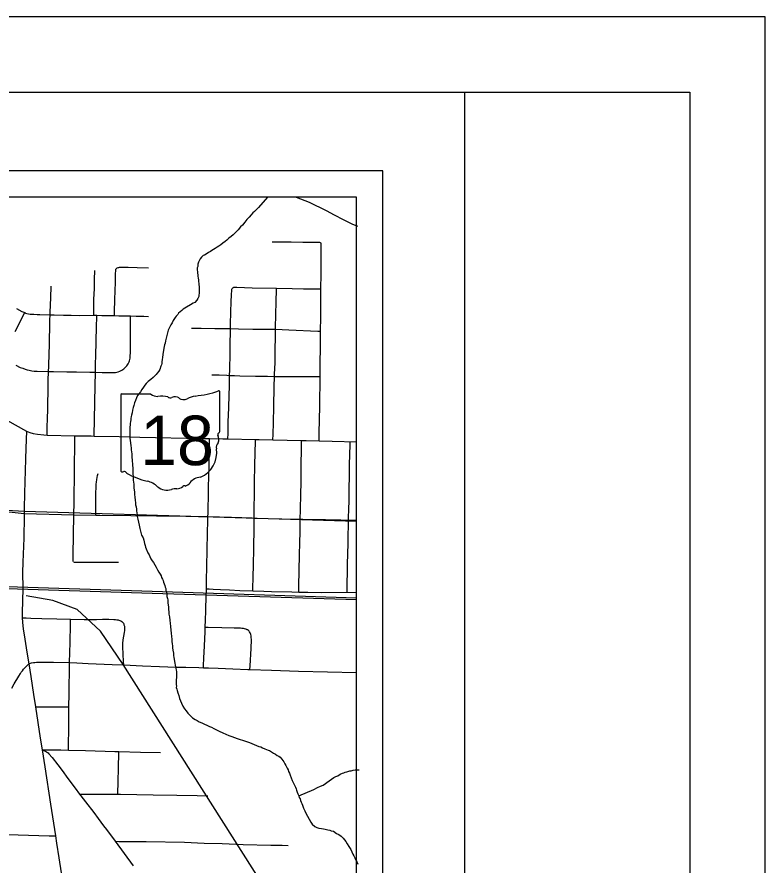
# Model space of a CAD drawing. Extents: x -483 to 680, y 0 to 440.
# Drawn here: x 580.4 to 680, y 327.1 to 440 of the extents above; entities that cross this region are included whole.
import ezdxf

# ---------------------------------------------------------------- set-up
doc = ezdxf.new("R2010")
doc.units = 0
for name, color, linetype in [('Default', 7, 'Continuous'), ('GM_X_City_Street', 7, 'Continuous'), ('GM_X_County_Road', 7, 'Continuous'), ('GM_X_Major_River', 7, 'Continuous'), ('GM_X_Minor_River', 7, 'Continuous'), ('GM_X_Rail_Line', 7, 'Continuous'), ('GM_X_State_Location', 7, 'Continuous'), ('GM_X_State_Route', 7, 'Continuous'), ('GM_X_State_Shield', 7, 'Continuous'), ('SH_Border', 7, 'Continuous'), ('SH_Cut_Line', 7, 'Continuous'), ('SH_Text', 7, 'Continuous')]:
    doc.layers.add(name, color=color, linetype=linetype)

msp = doc.modelspace()

# ---------------------------------------------------------------- linework, layer by layer
at = {"layer": 'Default'}
msp.add_lwpolyline([(436.43, 419.53), (436.43, 243.16), (629.12, 243.16), (629.12, 419.53)], close=True, dxfattribs=at)
at = {"layer": 'GM_X_City_Street'}
for points in [[(614.36, 410.08), (615.5, 410.07), (616.89, 410.05), (618.45, 410.03), (619.49, 410.02), (620.5, 410.02), (620.58, 410.01), (620.65, 410), (620.74, 409.96), (620.82, 409.91)], [(620.63, 383.55), (620.64, 384.65), (620.69, 388.13), (620.74, 392.15), (620.77, 393.85), (620.79, 396.02), (620.81, 398.16), (620.83, 400.03), (620.86, 403.61), (620.86, 403.8), (620.88, 405.77), (620.9, 407.99), (620.9, 409.72), (620.87, 409.83), (620.82, 409.91)], [(593.35, 400.24), (593.37, 400.72), (593.42, 402.39), (593.48, 404.69), (593.5, 405.82), (593.52, 406.24), (593.54, 406.33), (593.56, 406.41), (593.6, 406.47), (593.64, 406.53)], [(593.64, 406.53), (593.73, 406.59), (593.83, 406.63), (593.89, 406.65), (593.96, 406.66), (594.03, 406.67), (594.11, 406.67), (595.17, 406.67), (596.4, 406.64), (597.91, 406.6)], [(590.59, 400.28), (590.59, 400.76), (590.59, 401.61), (590.59, 402.37), (590.69, 403.83), (590.71, 404.46), (590.71, 405.04), (590.73, 406.26)], [(584.39, 384.34), (584.41, 385.24), (584.45, 386.67), (584.47, 387.59), (584.49, 388.67), (584.52, 390.06), (584.55, 391.6), (584.59, 392.81), (584.61, 393.47), (584.66, 395.28), (584.69, 396.23), (584.72, 397.47), (584.74, 398.32), (584.77, 399.63), (584.79, 400.34), (584.8, 400.68), (584.87, 402.6), (584.92, 404.17)], [(608.47, 383.81), (608.48, 384.52), (608.52, 386.11), (608.58, 387.96), (608.62, 389.69), (608.66, 390.8), (608.68, 391.85), (608.69, 392.28), (608.72, 393.03), (608.76, 395.24), (608.76, 395.98), (608.77, 396.81), (608.79, 397.82), (608.8, 398.5), (608.81, 399.04), (608.85, 400.73), (608.89, 402.06), (608.93, 403.02), (608.97, 403.62), (608.98, 403.71), (609.01, 403.78), (609.05, 403.85), (609.08, 403.9)], [(609.08, 403.9), (609.14, 403.95), (609.21, 403.99), (609.26, 404.01), (609.34, 404.02), (609.42, 404.02), (609.65, 404.02), (611.69, 403.95), (614.94, 403.89), (617.01, 403.84), (618.55, 403.82), (620.37, 403.8), (620.86, 403.8)], [(614.46, 383.69), (614.49, 384.41), (614.54, 385.99), (614.6, 388.14), (614.64, 390.75), (614.69, 392.15), (614.69, 392.43), (614.74, 393.97), (614.77, 395.77), (614.79, 397.32), (614.81, 398.42), (614.86, 400.56), (614.9, 401.91), (614.94, 403.89)], [(580.29, 401.19), (581.03, 400.8), (581.4, 400.63), (581.51, 400.58), (581.7, 400.51), (581.91, 400.47), (582.15, 400.45), (582.39, 400.43), (582.63, 400.41), (583.05, 400.39), (583.43, 400.38), (584.79, 400.34), (585.32, 400.33), (586.59, 400.3), (587.58, 400.28), (588.74, 400.27), (590.59, 400.28), (591, 400.28), (591.69, 400.27), (593.35, 400.24), (593.92, 400.23), (595.51, 400.19), (596.26, 400.17), (597.25, 400.15), (597.89, 400.14)], [(580.13, 398.11), (580.69, 399.21), (581.12, 400.06), (581.4, 400.63)], [(590.65, 384.2), (590.66, 384.86), (590.68, 385.86), (590.72, 387.12), (590.74, 387.98), (590.74, 388.71), (590.77, 390.9), (590.82, 392.69), (590.84, 393.75), (590.86, 394.97), (590.91, 396.71), (590.96, 398.86), (590.99, 399.92), (591, 400.28)], [(590.82, 392.69), (591.72, 392.67), (593.07, 392.65), (593.51, 392.68), (593.68, 392.7), (593.87, 392.76), (594.07, 392.84), (594.35, 392.99), (594.62, 393.16), (594.85, 393.36), (595.02, 393.54), (595.19, 393.8), (595.32, 394.08), (595.38, 394.23), (595.42, 394.38), (595.45, 394.55), (595.46, 394.71), (595.48, 395.44), (595.49, 395.99), (595.49, 396.3), (595.51, 397.73), (595.51, 398.6), (595.51, 399.31), (595.51, 400.19)], [(603.61, 398.57), (604.91, 398.57), (606.71, 398.54), (607.7, 398.53), (608.8, 398.5), (609.87, 398.47), (611.79, 398.44), (613.31, 398.44), (614.81, 398.42), (616.59, 398.34), (620.43, 398.18), (620.81, 398.16)], [(580.21, 393.64), (580.81, 393.35), (581.15, 393.22), (581.45, 393.11), (581.73, 393.02), (582, 392.97), (582.34, 392.89), (582.68, 392.85), (583.06, 392.83), (584.59, 392.81), (585.24, 392.81), (587, 392.76), (588.31, 392.73), (590.07, 392.69), (590.82, 392.69)], [(606.33, 392.37), (607.32, 392.34), (608.34, 392.29), (608.69, 392.28), (609.33, 392.25), (610.05, 392.22), (612.15, 392.18), (613.76, 392.16), (614.69, 392.15), (615.98, 392.15), (617.59, 392.15), (620.44, 392.15), (620.74, 392.15)], [(587.95, 373.72), (587.99, 375.36), (588.03, 379.72), (588.07, 383.54), (588.08, 384.25)], [(605.2, 353.36), (605.21, 353.65), (605.26, 354.63), (605.33, 356.26), (605.42, 358.13), (605.45, 358.77), (605.48, 359.7), (605.51, 360.91), (605.54, 361.62), (605.56, 362.31), (605.58, 363.03), (605.6, 363.65), (605.6, 363.88), (605.61, 364.8), (605.66, 367.03), (605.7, 368.86), (605.76, 371.43), (605.79, 372.78), (605.81, 373.47), (605.82, 373.91), (605.85, 374.72), (605.87, 376.06), (605.9, 377.53), (605.92, 378.7), (605.95, 380.26), (605.97, 381.95), (606, 383.46), (606.01, 383.86)], [(611.77, 363.6), (611.78, 364.13), (611.81, 365.2), (611.86, 367.28), (611.91, 368.96), (611.93, 369.76), (611.95, 371.5), (611.96, 372.7), (611.96, 373.29), (611.97, 373.82), (611.98, 374.71), (612, 376.39), (612.02, 378.24), (612.05, 380.09), (612.1, 382.18), (612.12, 383.29), (612.13, 383.75)], [(617.9, 363.42), (617.91, 364.17), (617.97, 366.35), (618.01, 368.35), (618.04, 370.01), (618.07, 371.39), (618.09, 372.59), (618.1, 373.14), (618.1, 373.35), (618.12, 374.14), (618.19, 376.75), (618.21, 377.74), (618.22, 378.86), (618.24, 380.58), (618.26, 382.22), (618.28, 383.22), (618.28, 383.6)], [(624.34, 363.43), (624.34, 363.62), (624.36, 364.73), (624.39, 365.96), (624.41, 367.15), (624.44, 368.54), (624.47, 369.9), (624.49, 371.09), (624.52, 372.17), (624.53, 373.02), (624.54, 373.48), (624.57, 374.29), (624.6, 375.76), (624.63, 377.37), (624.65, 378.74), (624.68, 380.39), (624.71, 381.76), (624.73, 383.03), (624.74, 383.46)], [(590.87, 373.69), (590.89, 376.71), (590.91, 377.28), (590.92, 377.57), (590.94, 377.81), (590.97, 378.07), (591.01, 378.43), (591.04, 378.7), (591.1, 378.95), (591.18, 379.2)], [(575.94, 374.46), (577.14, 374.35), (579.73, 374.07), (581.33, 373.9)], [(581.33, 373.9), (587.95, 373.72), (590.87, 373.69), (591.41, 373.69), (595.55, 373.64), (598.96, 373.6), (601.11, 373.58), (604.55, 373.5), (605.81, 373.47), (608.94, 373.38), (611.7, 373.3), (611.96, 373.29), (615.67, 373.19), (618.1, 373.14), (618.46, 373.14), (621.48, 373.08), (625.59, 372.99)], [(587.9, 367.46), (587.87, 367.54), (587.87, 368.36), (587.95, 373.72)], [(587.9, 367.46), (587.97, 367.42), (588.03, 367.41), (589.8, 367.42), (591.18, 367.41), (592.77, 367.41), (593.88, 367.41)], [(605.6, 363.88), (605.98, 363.85), (606.52, 363.81), (607.46, 363.77), (608.68, 363.72), (610.04, 363.66), (611.77, 363.6), (613.24, 363.55), (614.25, 363.51), (616.96, 363.44), (617.9, 363.42), (619.13, 363.4), (620.9, 363.37), (625.59, 363.42)], [(581.08, 360), (581.59, 359.98), (582.21, 359.96), (583.7, 359.92), (585.67, 359.86), (587.5, 359.81), (589.31, 359.77), (590.41, 359.76), (590.96, 359.78), (591.77, 359.8), (592.19, 359.81), (592.6, 359.82), (593.26, 359.79), (593.49, 359.77), (593.67, 359.75), (593.83, 359.72), (593.96, 359.68), (594.06, 359.65), (594.14, 359.61), (594.21, 359.58), (594.29, 359.53), (594.36, 359.49), (594.43, 359.43), (594.49, 359.37), (594.54, 359.31), (594.6, 359.22)], [(587.22, 342.39), (587.23, 342.73), (587.27, 345.58), (587.27, 347.63), (587.28, 348.17), (587.31, 349.9), (587.32, 350.95), (587.38, 352.81), (587.37, 353.47), (587.38, 354.04), (587.41, 355.4), (587.44, 356.7), (587.5, 359.13), (587.5, 359.31), (587.5, 359.81)], [(594.6, 353.72), (594.57, 354.2), (594.51, 355.18), (594.46, 356.16), (594.47, 356.59), (594.51, 357.08), (594.69, 358.04), (594.73, 358.33), (594.74, 358.6), (594.73, 358.72), (594.72, 358.84), (594.7, 358.94), (594.67, 359.03), (594.65, 359.13), (594.6, 359.22)], [(605.45, 358.77), (605.84, 358.76), (607.66, 358.71), (609.32, 358.66), (610.16, 358.65), (610.34, 358.64), (610.51, 358.62), (610.65, 358.58), (610.79, 358.54), (610.99, 358.44)], [(611.39, 353.13), (611.43, 353.63), (611.55, 355.92), (611.59, 357.1), (611.57, 357.39), (611.55, 357.6), (611.52, 357.76), (611.47, 357.9), (611.43, 358.01), (611.36, 358.12), (611.29, 358.22), (611.2, 358.31), (611.09, 358.38), (610.99, 358.44)], [(579.68, 350.64), (580.01, 351.19), (580.62, 352.23), (580.83, 352.59), (580.93, 352.76), (581.09, 352.96), (581.25, 353.15), (581.58, 353.52), (581.94, 353.86)], [(581.94, 353.86), (582.33, 353.99), (582.58, 354.05), (582.76, 354.07), (582.96, 354.09), (583.89, 354.08), (585.25, 354.09), (587.38, 354.04)], [(587.38, 354.04), (588.35, 354), (589.85, 353.94), (593.05, 353.79), (594.6, 353.72)], [(594.6, 353.72), (597.1, 353.63), (599.37, 353.54), (601.56, 353.45), (602.87, 353.42), (604.6, 353.39), (605.2, 353.36)], [(605.2, 353.36), (605.86, 353.34), (607.15, 353.29), (609.11, 353.2), (611.1, 353.14), (611.39, 353.13)], [(611.39, 353.13), (614.27, 353.03), (617.87, 352.9), (625.59, 352.74)], [(582.83, 348.17), (583.31, 348.17), (585.82, 348.17), (586.82, 348.17), (587.28, 348.17)], [(583.72, 342.41), (584.85, 342.41), (586.22, 342.42), (587.22, 342.39), (589.51, 342.32), (593.41, 342.21), (593.93, 342.2), (596.82, 342.13), (599.49, 342.05)], [(593.81, 336.5), (593.82, 336.88), (593.84, 337.9), (593.89, 340.28), (593.92, 341.74), (593.93, 342.2)], [(588.72, 336.53), (589.42, 336.52), (592.11, 336.52), (593.81, 336.5), (594.15, 336.5), (598.5, 336.44), (601.68, 336.39), (604.37, 336.33), (605.79, 336.29)], [(571.52, 331.38), (571.62, 331.37), (573.6, 331.3), (575.89, 331.25), (577.75, 331.18), (584.68, 330.98), (585.5, 330.96)], [(593.44, 330.25), (593.93, 330.24), (597.6, 330.2), (602.69, 330.12), (605.29, 330.02), (607.71, 329.95), (610.5, 329.84), (614.19, 329.75), (615.69, 329.72), (616.49, 329.69)]]:
    msp.add_lwpolyline(points, dxfattribs=at)
at = {"layer": 'GM_X_County_Road'}
msp.add_line((593.44, 330.25), (595.87, 326.99), dxfattribs=at)
for points in [[(583.72, 342.41), (584.05, 342.29), (584.32, 342.17), (584.44, 342.09), (584.52, 342.02), (584.64, 341.9), (585.05, 341.39), (585.81, 340.41), (586.38, 339.68), (587.16, 338.63), (588.12, 337.33), (588.72, 336.53)], [(588.72, 336.53), (588.9, 336.28), (589.49, 335.49), (590.59, 334.07), (591.18, 333.28), (591.92, 332.29), (592.28, 331.8), (593.44, 330.25)]]:
    msp.add_lwpolyline(points, dxfattribs=at)
at = {"layer": 'GM_X_Major_River'}
msp.add_lwpolyline([(617.56, 415.99), (619.31, 415.35), (621.56, 414.23), (622.6, 413.64), (623.8, 413.04), (624.96, 412.47), (625.74, 412.15)], dxfattribs=at)
at = {"layer": 'GM_X_Minor_River'}
for points in [[(613.75, 415.99), (612.53, 414.64), (612.29, 414.38), (612.02, 414.12), (611.78, 413.9), (611.55, 413.64), (611.31, 413.34), (611, 413.05), (610.72, 412.67), (610.41, 412.3), (610.14, 412.04), (609.82, 411.67), (609.47, 411.3), (609.16, 411.01), (608.88, 410.75), (608.61, 410.53), (608.34, 410.27), (608.1, 410.09), (607.79, 409.87), (607.52, 409.65), (607.25, 409.5), (607.02, 409.36), (606.79, 409.18), (606.55, 409.03), (606.32, 408.92), (606.13, 408.78), (605.9, 408.63), (605.7, 408.52), (605.35, 408.3), (605.16, 408.23), (604.97, 408.01), (604.77, 407.79), (604.69, 407.6), (604.57, 407.34), (604.48, 407.07), (604.44, 406.77), (604.39, 406.58), (604.38, 406.28), (604.42, 406.09), (604.47, 405.44), (604.51, 405.25), (604.54, 404.94), (604.57, 404.75), (604.6, 404.56), (604.59, 404.37), (604.62, 404.07), (604.62, 403.8), (604.65, 403.5), (604.64, 403.23), (604.59, 402.97), (604.59, 402.78), (604.46, 402.51), (604.34, 402.29), (604.07, 401.99), (603.84, 401.88), (603.49, 401.67), (602.95, 401.38), (602.72, 401.23), (602.52, 401.09), (602.33, 400.9), (602.13, 400.72), (601.9, 400.57), (601.78, 400.38), (601.59, 400.16), (601.43, 399.98), (601.19, 399.57), (601.03, 399.27), (600.87, 399), (600.71, 398.74), (600.59, 398.48), (600.51, 398.29), (600.42, 397.95), (600.33, 397.57), (600.25, 397.24), (600.16, 396.9), (600.11, 396.59), (600.03, 396.33), (599.99, 396.14), (599.94, 395.91), (599.8, 395.04), (599.75, 394.66), (599.71, 394.4), (599.66, 394.1), (599.66, 393.87), (599.61, 393.68), (599.53, 393.49), (599.4, 393.08), (599.25, 392.82), (599.05, 392.59), (598.89, 392.41), (598.73, 392.22), (598.5, 392), (598.19, 391.71), (597.84, 391.45), (597.6, 391.19), (597.41, 390.97), (597.21, 390.71), (597.01, 390.41), (596.81, 390.11)], [(596.81, 390.11), (596.61, 389.81), (596.42, 389.59), (596.29, 389.29), (596.17, 388.95), (596.01, 388.61), (595.92, 388.27), (595.84, 388.01), (595.75, 387.63), (595.7, 387.29), (595.62, 386.99), (595.58, 386.8), (595.53, 386.54), (595.53, 386.35), (595.48, 386.16), (595.47, 385.89), (595.43, 385.66), (595.42, 385.44), (595.42, 385.21), (595.41, 384.98), (595.4, 384.75), (595.4, 384.49), (595.39, 384.14), (595.42, 383.88), (595.45, 383.65), (595.54, 382.88), (595.57, 382.62), (595.6, 382.35), (595.66, 381.82), (595.65, 381.59), (595.68, 381.36), (595.71, 381.05), (595.71, 380.83), (595.74, 380.56), (595.77, 380.29), (595.8, 379.99), (595.79, 379.72), (595.82, 379.42), (595.81, 379.11), (595.84, 378.85), (595.87, 378.58), (595.86, 378.35), (595.89, 378.08), (595.92, 377.78), (595.95, 377.51), (595.95, 377.28), (595.98, 377.05), (596.01, 376.75), (596.03, 376.41), (596.06, 376.06), (596.13, 375.68), (596.15, 375.3), (596.18, 375.03), (596.25, 374.8), (596.28, 374.46), (596.31, 374.23), (596.34, 373.96), (596.37, 373.7), (596.4, 373.47), (596.47, 373.12), (596.54, 372.74), (596.64, 372.32), (596.74, 371.9), (596.84, 371.52), (596.98, 371.02), (597.16, 370.67), (597.26, 370.36), (597.33, 370.1), (597.37, 369.9), (597.43, 369.64), (597.5, 369.41), (597.57, 369.18), (597.82, 368.64), (597.97, 368.37), (598.07, 368.17), (598.22, 367.87), (598.4, 367.59), (598.54, 367.36), (598.73, 367.05), (598.91, 366.74), (599.09, 366.4), (599.27, 366.09), (599.45, 365.81), (599.56, 365.58), (599.63, 365.35), (599.77, 365.16), (599.84, 364.97), (599.91, 364.77), (599.98, 364.54), (600.05, 364.31), (600.12, 364.08), (600.19, 363.89), (600.22, 363.66), (600.29, 363.47), (600.32, 363.13), (600.35, 362.86), (600.42, 362.59), (600.45, 362.4), (600.45, 362.21), (600.48, 361.94), (600.51, 361.72)], [(600.51, 361.72), (600.54, 361.41), (600.57, 361.11), (600.6, 360.8), (600.62, 360.5), (600.69, 360.15), (600.71, 359.66), (600.78, 359.31), (600.8, 358.86), (600.87, 358.36), (600.93, 357.94), (600.96, 357.52), (600.98, 357.14), (601.01, 356.83), (601.04, 356.53), (601.07, 356.26), (601.1, 356), (601.13, 355.69), (601.2, 355.31), (601.22, 355), (601.26, 354.74), (601.38, 353.97), (601.45, 353.7), (601.48, 353.47), (601.55, 353.28), (601.59, 353.05), (601.62, 352.86), (601.61, 352.56), (601.64, 352.33), (601.63, 352.1), (601.58, 351.68), (601.58, 351.49), (601.57, 351.3), (601.57, 351.11), (601.6, 350.92), (601.59, 350.73), (601.66, 350.5), (601.73, 350.31), (601.8, 350.01), (601.91, 349.66), (602.01, 349.28), (602.15, 348.97), (602.29, 348.62), (602.47, 348.24), (602.69, 347.89), (602.91, 347.62), (603.13, 347.31), (603.31, 347.11), (603.54, 346.91), (603.76, 346.68), (604.09, 346.48), (604.39, 346.32), (604.65, 346.16), (604.99, 346), (605.33, 345.84), (605.67, 345.71), (606, 345.55), (606.3, 345.43), (606.6, 345.27), (606.94, 345.1), (607.31, 344.9), (607.8, 344.7), (608.18, 344.5), (608.59, 344.33), (609, 344.21), (609.34, 344.05), (609.72, 343.92), (610.09, 343.8), (610.39, 343.71), (610.66, 343.63), (611.33, 343.38), (611.67, 343.26), (611.97, 343.13), (612.27, 343.01), (612.57, 342.89), (612.84, 342.81), (613.06, 342.69), (613.4, 342.56), (613.62, 342.48), (613.81, 342.4), (614, 342.32), (614.26, 342.16), (614.52, 342), (614.82, 341.84), (615.04, 341.68), (615.23, 341.56), (615.42, 341.44), (615.64, 341.2), (615.78, 341.01), (615.93, 340.82), (616.04, 340.58), (616.18, 340.35), (616.36, 339.97), (616.47, 339.74), (616.54, 339.54), (616.65, 339.31), (616.75, 339.04), (616.89, 338.7), (617.04, 338.35), (617.22, 338), (617.32, 337.7)], [(617.89, 336.31), (619.89, 337.13), (620.39, 337.42), (620.81, 337.59), (621.16, 337.74), (621.93, 338.28), (622.28, 338.54), (622.59, 338.72), (622.86, 338.87), (623.09, 338.97), (623.29, 339.08), (623.52, 339.23), (623.71, 339.3), (623.9, 339.37), (624.1, 339.44), (624.29, 339.51), (624.71, 339.61), (624.9, 339.64), (625.13, 339.71), (625.4, 339.74), (625.66, 339.77), (625.93, 339.77)], [(617.32, 337.7), (617.47, 337.46), (617.54, 337.23), (617.61, 337.04), (617.68, 336.81), (617.78, 336.58), (617.89, 336.31), (617.96, 336.08), (618.07, 335.89), (618.14, 335.66), (618.24, 335.46), (618.31, 335.27), (618.38, 335.04), (618.52, 334.66), (618.7, 334.31), (618.88, 333.92), (619.06, 333.58), (619.5, 332.8), (619.68, 332.53), (620.05, 332.22), (620.31, 332.1), (620.58, 332.01), (620.92, 331.96), (621.18, 331.92), (621.44, 331.87), (621.78, 331.79), (622.05, 331.74), (622.24, 331.66), (622.54, 331.58), (622.91, 331.3), (623.13, 331.18), (623.36, 331.06), (623.54, 330.94), (623.8, 330.66), (623.99, 330.43), (624.17, 330.2), (624.35, 329.89), (624.57, 329.54), (624.82, 329.15), (624.97, 328.84), (625.11, 328.54), (625.22, 328.3), (625.36, 328.03), (625.47, 327.84), (625.54, 327.65), (625.68, 327.42), (625.79, 327.19)]]:
    msp.add_lwpolyline(points, dxfattribs=at)
at = {"layer": 'GM_X_Rail_Line'}
for points in [[(504.3, 415.99), (522.25, 407.1), (513.56, 388.84), (526.04, 382.84), (527.79, 386.04), (538.34, 380.62), (542.42, 378.93), (550.52, 376.65), (572.63, 374.77), (575.77, 374.5), (581.36, 374.21), (607.95, 373.4), (625.59, 372.87)], [(439.96, 352.71), (452.5, 355.46), (461.13, 357.53), (469.14, 359.27), (480.56, 361.86), (486.75, 363.27), (492.56, 364.47), (499.08, 365.53), (505.43, 366.06), (510.22, 366.31), (531.19, 365.74), (558.34, 364.83), (598.4, 363.55), (625.59, 362.68)], [(439.96, 352.42), (440.63, 352.6), (452.55, 355.22), (461.19, 357.29), (469.19, 359.02), (480.62, 361.62), (486.8, 363.02), (492.6, 364.23), (499.11, 365.29), (505.45, 365.81), (510.22, 366.07), (531.18, 365.49), (558.33, 364.58), (598.39, 363.3), (625.59, 362.43)], [(626.19, 297.17), (621.23, 308.64), (614.31, 322.6), (594.5, 353.77), (591.52, 358.24), (588.4, 361.09), (585.15, 362.31), (581.62, 362.93)]]:
    msp.add_lwpolyline(points, dxfattribs=at)
at = {"layer": 'GM_X_State_Route'}
for points in [[(578.33, 386.67), (579.04, 386.31), (581.64, 384.85)], [(581.64, 384.85), (581.55, 382.6), (581.5, 381.11), (581.39, 376.61), (581.33, 374.57), (581.33, 373.9), (581.32, 372.46), (581.31, 371.65), (581.27, 370.59), (581.16, 367.39), (581.11, 366.02), (581.14, 363.95)], [(581.64, 384.85), (582.1, 384.68), (582.55, 384.56), (583.12, 384.46), (583.93, 384.37), (584.39, 384.34), (588.08, 384.25), (588.59, 384.24), (590.27, 384.21), (590.65, 384.2), (594, 384.13), (596.73, 384.07), (605.05, 383.88), (606.01, 383.86), (607.78, 383.82), (608.47, 383.81), (612.13, 383.75), (612.62, 383.74), (614.46, 383.69), (618.28, 383.6), (618.89, 383.59), (620.63, 383.55), (622.37, 383.52), (625.59, 383.45)], [(581.14, 363.95), (581.14, 363.85), (581.11, 362.29), (581.06, 360.68), (581.08, 360), (581.12, 359.42), (581.22, 358.48), (581.33, 357.74), (581.69, 355.45), (581.94, 353.86), (582.21, 352.17), (582.58, 349.77), (582.83, 348.17), (583.48, 344), (583.72, 342.41)], [(583.72, 342.41), (584.07, 340.17), (584.83, 335.17), (585.5, 330.96), (585.65, 330.02), (585.96, 328.06), (586.28, 326.05), (586.43, 325.13), (586.7, 323.32), (586.75, 322.92), (587.66, 317.21), (588.86, 309.69), (588.98, 308.92), (590.25, 300.75), (591.1, 295.35), (591.5, 292.96), (592.1, 288.96), (593.07, 282.9)]]:
    msp.add_lwpolyline(points, dxfattribs=at)
at = {"layer": 'GM_X_State_Shield'}
for p, q in [((594.2, 389.63), (594.2, 379.62)), ((598.19, 389.8), (594.33, 389.8)), ((607.38, 384.81), (607.38, 390.05)), ((607.38, 384.82), (607.38, 384.81))]:
    msp.add_line(p, q, dxfattribs=at)
for centre, radius, start, end in [((594.35, 389.65), 0.153, 98.1301, 188.1301), ((599.11, 390.96), 1.48, 231.6195, 271.1119), ((602.69, 403.44), 13.98, 275.8445, 288.9065), ((607.24, 390.07), 0.147, 351.8621, 97.738), ((599.6, 384.18), 5.32, 80.4867, 94.9883), ((600.81, 389.7), 0.427, 219.7921, 297.1024), ((601.44, 388.55), 0.889, 54.4667, 119.1411), ((602.58, 390.13), 1.07, 233.8562, 294.8282), ((604.47, 386.74), 2.81, 97.3462, 120.7689), ((607.35, 384.43), 0.227, 107.944, 210.337), ((605.9, 383.77), 1.36, 340.033, 23.6496), ((607.23, 384.79), 0.157, 289.6038, 7.7341), ((607.91, 382.62), 0.992, 136.8065, 186.9296), ((603.47, 381.96), 3.5, 292.3089, 8.9858), ((594.35, 379.6), 0.154, 171.9584, 258.3066), ((594.38, 380.62), 1.18, 267.339, 280.6039), ((594.62, 379.05), 0.424, 29.7484, 93.2717), ((599.97, 388.04), 10.1, 240.4129, 257.1985), ((604.94, 376.81), 1.92, 94.4031, 142.5768), ((596.96, 375.13), 3.16, 47.1842, 75.836), ((600.38, 379), 2, 230.7004, 286.2918), ((601.53, 375.54), 1.65, 85.6951, 111.2099), ((601.68, 378.25), 1.07, 268.777, 315.5493), ((602.65, 377.28), 0.301, 65.7517, 132.6484), ((602.52, 378.65), 1.13, 282.8732, 323.2771)]:
    msp.add_arc(centre, radius, start, end, dxfattribs=at)
at = {"layer": 'SH_Border'}
msp.add_line((640, 10), (640, 430), dxfattribs=at)
msp.add_lwpolyline([(30, 430), (670, 430), (670, 10), (30, 10)], close=True, dxfattribs=at)
at = {"layer": 'SH_Cut_Line'}
msp.add_lwpolyline([(0, 0), (680, 0), (680, 440), (0, 440)], close=True, dxfattribs=at)
at = {"layer": 'SH_Text'}
msp.add_lwpolyline([(439.96, 246.7), (625.59, 246.7), (625.59, 415.99), (439.96, 415.99)], close=True, dxfattribs=at)
msp.add_lwpolyline([(439.96, 246.7), (625.59, 246.7), (625.59, 415.99), (439.96, 415.99)], close=True, dxfattribs=at)

# ---------------------------------------------------------------- texts
at = {"layer": 'GM_X_State_Location'}
msp.add_text('18', height=0.00947, rotation=0, dxfattribs=at).set_placement((598.26, 383.27))
at = {"layer": 'GM_X_State_Shield'}
msp.add_text('18', height=6.592, dxfattribs=at).set_placement((596.79, 380.33))

doc.saveas('drawing.dxf')
